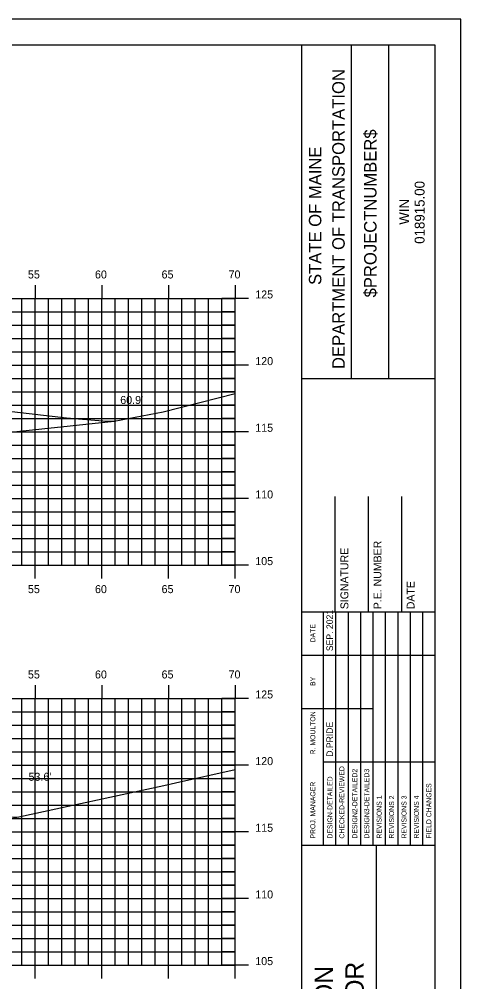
# Model space of a CAD drawing. Extents: x 853734 to 853906, y 365624 to 365734.
# Drawn here: x 853871.1 to 853904.2, y 365661.8 to 365734 of the extents above; entities that cross this region are included whole.
import ezdxf

# ---------------------------------------------------------------- set-up
doc = ezdxf.new("R2010")
doc.units = 0
for name, color, linetype in [('BORDER', 7, 'Continuous'), ('D_Roadway_Centerline', 7, 'Continuous'), ('D_Text_Standard', 7, 'Continuous'), ('H_V ANNOTATION', 7, 'Continuous'), ('MAJOR', 7, 'Continuous'), ('MINOR', 7, 'Continuous'), ('PLOT BOUNDARY', 7, 'Continuous'), ('S_Roadway_Centerline', 7, 'Continuous')]:
    doc.layers.add(name, color=color, linetype=linetype)

msp = doc.modelspace()

# ---------------------------------------------------------------- linework, layer by layer
at = {"layer": 'BORDER'}
for p, q in [((853892.331, 365627.027), (853892.331, 365732.027)), ((853896.06, 365707.024), (853896.06, 365732.024)), ((853898.855, 365707.024), (853898.855, 365732.024)), ((853892.332, 365707.021), (853902.331, 365707.021)), ((853894.831, 365689.53), (853894.831, 365698.177)), ((853897.331, 365689.53), (853897.331, 365698.177)), ((853899.831, 365689.53), (853899.831, 365698.177)), ((853892.331, 365689.53), (853902.331, 365689.53)), ((853892.331, 365672.03), (853902.331, 365672.03)), ((853897.922, 365637.03), (853897.922, 365672.03))]:
    msp.add_line(p, q, dxfattribs=at)
msp.add_lwpolyline([(853742.331, 365627.027), (853902.331, 365627.027), (853902.331, 365732.027), (853742.331, 365732.027)], close=True, dxfattribs=at)
for points in [[(853893.946, 365686.28), (853893.946, 365689.53)], [(853894.879, 365672.033), (853894.879, 365689.53)], [(853895.81, 365689.53), (853895.81, 365672.033)], [(853896.742, 365672.033), (853896.742, 365689.53)], [(853897.674, 365672.033), (853897.674, 365689.53)], [(853898.606, 365672.033), (853898.606, 365689.53)], [(853899.537, 365672.033), (853899.537, 365689.53)], [(853900.469, 365672.033), (853900.469, 365689.53)], [(853901.401, 365672.033), (853901.401, 365689.53)], [(853893.947, 365672.033), (853893.947, 365688.824)], [(853892.331, 365686.28), (853902.331, 365686.28)], [(853892.331, 365682.28), (853893.947, 365682.28)], [(853893.946, 365682.28), (853897.673, 365682.28)], [(853893.946, 365678.28), (853902.331, 365678.28)]]:
    msp.add_lwpolyline(points, dxfattribs=at)
at = {"layer": 'D_Roadway_Centerline'}
msp.add_line((853850.691, 365700.915), (853878.26, 365703.831), dxfattribs=at)
at = {"layer": 'MAJOR'}
for p, q in [((853872.331, 365714.029), (853872.331, 365713.027)), ((853877.331, 365714.029), (853877.331, 365713.027)), ((853882.331, 365714.029), (853882.331, 365713.027)), ((853887.331, 365714.029), (853887.331, 365713.027)), ((853747.331, 365713.027), (853887.331, 365713.027)), ((853747.331, 365713.027), (853887.331, 365713.027)), ((853872.331, 365693.027), (853872.331, 365713.027)), ((853877.331, 365693.027), (853877.331, 365713.027)), ((853882.331, 365693.027), (853882.331, 365713.027)), ((853888.333, 365713.027), (853886.329, 365713.027)), ((853887.331, 365693.027), (853887.331, 365713.027)), ((853887.331, 365693.027), (853887.331, 365713.027)), ((853747.331, 365708.027), (853887.331, 365708.027)), ((853888.333, 365708.027), (853886.329, 365708.027)), ((853747.331, 365703.027), (853887.331, 365703.027)), ((853888.333, 365703.027), (853886.329, 365703.027)), ((853747.331, 365698.027), (853887.331, 365698.027)), ((853888.333, 365698.027), (853886.329, 365698.027)), ((853747.331, 365693.027), (853887.331, 365693.027)), ((853747.331, 365693.027), (853887.331, 365693.027)), ((853872.331, 365692.025), (853872.331, 365693.027)), ((853877.331, 365692.025), (853877.331, 365693.027)), ((853882.331, 365692.025), (853882.331, 365693.027)), ((853888.333, 365693.027), (853886.329, 365693.027)), ((853887.331, 365692.025), (853887.331, 365693.027)), ((853872.331, 365684.029), (853872.331, 365683.027)), ((853877.331, 365684.029), (853877.331, 365683.027)), ((853882.331, 365684.029), (853882.331, 365683.027)), ((853887.331, 365684.029), (853887.331, 365683.027)), ((853747.331, 365683.027), (853887.331, 365683.027)), ((853747.331, 365683.027), (853887.331, 365683.027)), ((853872.331, 365663.027), (853872.331, 365683.027)), ((853877.331, 365663.027), (853877.331, 365683.027)), ((853882.331, 365663.027), (853882.331, 365683.027)), ((853888.333, 365683.027), (853886.329, 365683.027)), ((853887.331, 365663.027), (853887.331, 365683.027)), ((853887.331, 365663.027), (853887.331, 365683.027)), ((853747.331, 365678.027), (853887.331, 365678.027)), ((853888.333, 365678.027), (853886.329, 365678.027)), ((853747.331, 365673.027), (853887.331, 365673.027)), ((853888.333, 365673.027), (853886.329, 365673.027)), ((853747.331, 365668.027), (853887.331, 365668.027)), ((853888.333, 365668.027), (853886.329, 365668.027)), ((853747.331, 365663.027), (853887.331, 365663.027)), ((853747.331, 365663.027), (853887.331, 365663.027)), ((853872.331, 365662.025), (853872.331, 365663.027)), ((853877.331, 365662.025), (853877.331, 365663.027)), ((853882.331, 365662.025), (853882.331, 365663.027)), ((853888.333, 365663.027), (853886.329, 365663.027)), ((853887.331, 365662.025), (853887.331, 365663.027))]:
    msp.add_line(p, q, dxfattribs=at)
at = {"layer": 'MINOR'}
for p, q in [((853871.331, 365693.027), (853871.331, 365713.027)), ((853873.331, 365693.027), (853873.331, 365713.027)), ((853874.331, 365693.027), (853874.331, 365713.027)), ((853875.331, 365693.027), (853875.331, 365713.027)), ((853876.331, 365693.027), (853876.331, 365713.027)), ((853878.331, 365693.027), (853878.331, 365713.027)), ((853879.331, 365693.027), (853879.331, 365713.027)), ((853880.331, 365693.027), (853880.331, 365713.027)), ((853881.331, 365693.027), (853881.331, 365713.027)), ((853883.331, 365693.027), (853883.331, 365713.027)), ((853884.331, 365693.027), (853884.331, 365713.027)), ((853885.331, 365693.027), (853885.331, 365713.027)), ((853886.331, 365693.027), (853886.331, 365713.027)), ((853747.331, 365712.027), (853887.331, 365712.027)), ((853887.331, 365712.027), (853886.329, 365712.027)), ((853747.331, 365711.027), (853887.331, 365711.027)), ((853887.331, 365711.027), (853886.329, 365711.027)), ((853747.331, 365710.027), (853887.331, 365710.027)), ((853887.331, 365710.027), (853886.329, 365710.027)), ((853747.331, 365709.027), (853887.331, 365709.027)), ((853887.331, 365709.027), (853886.329, 365709.027)), ((853747.331, 365707.027), (853887.331, 365707.027)), ((853887.331, 365707.027), (853886.329, 365707.027)), ((853747.331, 365706.027), (853887.331, 365706.027)), ((853887.331, 365706.027), (853886.329, 365706.027)), ((853747.331, 365705.027), (853887.331, 365705.027)), ((853887.331, 365705.027), (853886.329, 365705.027)), ((853747.331, 365704.027), (853887.331, 365704.027)), ((853887.331, 365704.027), (853886.329, 365704.027)), ((853747.331, 365702.027), (853887.331, 365702.027)), ((853887.331, 365702.027), (853886.329, 365702.027)), ((853747.331, 365701.027), (853887.331, 365701.027)), ((853887.331, 365701.027), (853886.329, 365701.027)), ((853747.331, 365700.027), (853887.331, 365700.027)), ((853887.331, 365700.027), (853886.329, 365700.027)), ((853747.331, 365699.027), (853887.331, 365699.027)), ((853887.331, 365699.027), (853886.329, 365699.027)), ((853747.331, 365697.027), (853887.331, 365697.027)), ((853887.331, 365697.027), (853886.329, 365697.027)), ((853747.331, 365696.027), (853887.331, 365696.027)), ((853887.331, 365696.027), (853886.329, 365696.027)), ((853747.331, 365695.027), (853887.331, 365695.027)), ((853887.331, 365695.027), (853886.329, 365695.027)), ((853747.331, 365694.027), (853887.331, 365694.027)), ((853887.331, 365694.027), (853886.329, 365694.027)), ((853871.331, 365663.027), (853871.331, 365683.027)), ((853873.331, 365663.027), (853873.331, 365683.027)), ((853874.331, 365663.027), (853874.331, 365683.027)), ((853875.331, 365663.027), (853875.331, 365683.027)), ((853876.331, 365663.027), (853876.331, 365683.027)), ((853878.331, 365663.027), (853878.331, 365683.027)), ((853879.331, 365663.027), (853879.331, 365683.027)), ((853880.331, 365663.027), (853880.331, 365683.027)), ((853881.331, 365663.027), (853881.331, 365683.027)), ((853883.331, 365663.027), (853883.331, 365683.027)), ((853884.331, 365663.027), (853884.331, 365683.027)), ((853885.331, 365663.027), (853885.331, 365683.027)), ((853886.331, 365663.027), (853886.331, 365683.027)), ((853747.331, 365682.027), (853887.331, 365682.027)), ((853887.331, 365682.027), (853886.329, 365682.027)), ((853747.331, 365681.027), (853887.331, 365681.027)), ((853887.331, 365681.027), (853886.329, 365681.027)), ((853747.331, 365680.027), (853887.331, 365680.027)), ((853887.331, 365680.027), (853886.329, 365680.027)), ((853747.331, 365679.027), (853887.331, 365679.027)), ((853887.331, 365679.027), (853886.329, 365679.027)), ((853747.331, 365677.027), (853887.331, 365677.027)), ((853887.331, 365677.027), (853886.329, 365677.027)), ((853747.331, 365676.027), (853887.331, 365676.027)), ((853887.331, 365676.027), (853886.329, 365676.027)), ((853747.331, 365675.027), (853887.331, 365675.027)), ((853887.331, 365675.027), (853886.329, 365675.027)), ((853747.331, 365674.027), (853887.331, 365674.027)), ((853887.331, 365674.027), (853886.329, 365674.027)), ((853747.331, 365672.027), (853887.331, 365672.027)), ((853887.331, 365672.027), (853886.329, 365672.027)), ((853747.331, 365671.027), (853887.331, 365671.027)), ((853887.331, 365671.027), (853886.329, 365671.027)), ((853747.331, 365670.027), (853887.331, 365670.027)), ((853887.331, 365670.027), (853886.329, 365670.027)), ((853747.331, 365669.027), (853887.331, 365669.027)), ((853887.331, 365669.027), (853886.329, 365669.027)), ((853747.331, 365667.027), (853887.331, 365667.027)), ((853887.331, 365667.027), (853886.329, 365667.027)), ((853747.331, 365666.027), (853887.331, 365666.027)), ((853887.331, 365666.027), (853886.329, 365666.027)), ((853747.331, 365665.027), (853887.331, 365665.027)), ((853887.331, 365665.027), (853886.329, 365665.027)), ((853747.331, 365664.027), (853887.331, 365664.027)), ((853887.331, 365664.027), (853886.329, 365664.027))]:
    msp.add_line(p, q, dxfattribs=at)
at = {"layer": 'PLOT BOUNDARY'}
msp.add_lwpolyline([(853734.238, 365623.968), (853904.238, 365623.968), (853904.238, 365733.968), (853734.238, 365733.968)], close=True, dxfattribs=at)
at = {"layer": 'S_Roadway_Centerline'}
for points in [[(853812.276, 365705.044), (853815.177, 365704.969), (853815.27, 365704.964), (853815.339, 365704.953), (853832.608, 365701.211), (853833.575, 365700.998), (853833.71, 365700.979), (853833.733, 365700.958), (853834.393, 365700.789), (853836.025, 365701.316), (853846.123, 365704.679), (853857.205, 365705.747), (853860.019, 365705.778), (853864.274, 365705.275), (853871.878, 365704.404), (853874.679, 365704.062), (853877.708, 365703.82), (853878.26, 365703.831), (853881.928, 365704.53), (853887.331, 365705.898)], [(853811.863, 365675.837), (853813.755, 365675.697), (853821.827, 365675.24), (853824.464, 365674.566), (853827.275, 365673.871), (853830.33, 365673.374), (853838.95, 365671.586), (853839.68, 365671.539), (853839.755, 365671.509), (853841.878, 365672.13), (853846.275, 365673.685), (853850.313, 365673.969), (853859.98, 365675.212), (853865.378, 365674.554), (853870.715, 365674.134), (853870.947, 365674.131), (853871.098, 365674.158), (853881.972, 365676.502), (853882.85, 365676.699), (853887.331, 365677.689)]]:
    msp.add_lwpolyline(points, dxfattribs=at)

# ---------------------------------------------------------------- texts
at = {"layer": 'BORDER'}
for s, height, p in [('DEPARTMENT OF TRANSPORTATION', 0.93176, (853895.538, 365707.733)), ('$PROJECTNUMBER$', 0.93176, (853897.923, 365713.106)), ('STATE OF MAINE', 0.93176, (853893.787, 365714.039)), ('018915.00', 0.7453, (853901.527, 365717.125)), ('WIN', 0.7453, (853900.368, 365718.557)), ('P.E. NUMBER', 0.59055, (853898.292, 365689.722)), ('SIGNATURE', 0.5906, (853895.812, 365689.722)), ('DATE', 0.5906, (853900.772, 365689.722)), ('SEP. 2021', 0.4845, (853894.654, 365686.575)), ('DATE', 0.3714, (853893.336, 365687.235)), ('BY', 0.3714, (853893.336, 365683.965)), ('R. MOULTON', 0.3727, (853893.335, 365678.832)), ('D.PRIDE', 0.4845, (853894.654, 365678.653)), ('CHECKED-REVIEWED', 0.37275, (853895.512, 365672.518)), ('DESIGN2-DETAILED2', 0.37275, (853896.481, 365672.518)), ('DESIGN3-DETAILED3', 0.37275, (853897.376, 365672.518)), ('DESIGN-DETAILED', 0.37275, (853894.618, 365672.518)), ('PROJ. MANAGER', 0.37275, (853893.336, 365672.518)), ('FIELD CHANGES', 0.37275, (853902.034, 365672.518)), ('REVISIONS 1', 0.37275, (853898.307, 365672.518)), ('REVISIONS 2', 0.37275, (853899.239, 365672.518)), ('REVISIONS 3', 0.37275, (853900.171, 365672.518)), ('REVISIONS 4', 0.37275, (853901.102, 365672.518)), ('I-395/ROUTE 9 CONNECTOR', 1.37787, (853896.966, 365638.192)), ('BREWER TO EDDINGTON', 1.37787, (853894.665, 365640.231))]:
    msp.add_text(s, height=height, rotation=90, dxfattribs=at).set_placement(p)
at = {"layer": 'D_Text_Standard'}
for s, p in [("60.9'", (853878.709, 365705.113)), ("53.6'", (853871.833, 365676.854))]:
    msp.add_text(s, height=0.6, dxfattribs=at).set_placement(p)
at = {"layer": 'H_V ANNOTATION'}
for s, p in [('55', (853871.788, 365714.527)), ('60', (853876.817, 365714.527)), ('65', (853881.809, 365714.527)), ('70', (853886.833, 365714.527)), ('125', (853888.831, 365713.027)), ('120', (853888.831, 365708.027)), ('115', (853888.831, 365703.027)), ('110', (853888.831, 365698.027)), ('105', (853888.831, 365693.027)), ('55', (853871.788, 365690.927)), ('60', (853876.817, 365690.927)), ('65', (853881.809, 365690.927)), ('70', (853886.833, 365690.927)), ('55', (853871.788, 365684.527)), ('60', (853876.817, 365684.527)), ('65', (853881.809, 365684.527)), ('70', (853886.833, 365684.527)), ('125', (853888.831, 365683.027)), ('120', (853888.831, 365678.027)), ('115', (853888.831, 365673.027)), ('110', (853888.831, 365668.027)), ('105', (853888.831, 365663.027))]:
    msp.add_text(s, height=0.6, dxfattribs=at).set_placement(p)

doc.saveas('drawing.dxf')
